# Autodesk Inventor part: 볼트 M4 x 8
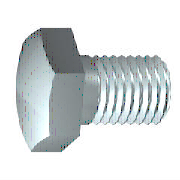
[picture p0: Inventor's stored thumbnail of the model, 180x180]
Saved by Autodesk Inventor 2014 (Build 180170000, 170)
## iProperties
Created: 2012-02
Part Number: 볼트 M4 x 8
Material: 스테인리스강
Description: 6각 머리 나사
Document SubType Name: Modeling
Standard: ISO 4017
Designer: mduedu
Standard Revision: Third edition 1999-08-15
Standards Organization: ISO
Language: ko-KR
Size Designation: M4 x 10
Categories: <MemberInstance><Categories><Category DisplayName="조임쇠" InternalName="e4da775c-781d-43d5-af7c-5136215cf5a6" Mnemonic="FSTN"><Category DisplayName="볼트" InternalN
Density: 8.08 g/cm^3
Appearance: 반광택
IsCustomPart: 0
Author: mduedu
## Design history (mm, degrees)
sketch "스케치1"
  geometry: L1 (0, 3.015)-(0, 2); L2 (1.75, 2)-(8, 2); L3 (8, 2)-(8, 0); L4 (8, 0)-(-0.4, 0); L5 (-2.08, 0)-(9.68, 0) reference; L6 (-0.4, 0)-(-0.4, 3.015); L7 (-0.4, 3.015)-(0, 3.015); L8 (1.75, 2)-(1.32, 2); L9 (1.32, 2)-(0, 2); L10 (0, -0.603)-(0, 3.618) reference
  constraints: 16 end point, 2 collinear, 2 perpendicular, 1 parallel
  dimensions: "d0" = 8 distance between parallel lines of L3 L1 (= NLG); "d1" = 6.25 distance from line of L2.start L3 (= GEL); "d2" = 4 diameter of L2 L4 (= GD); "d9" = 0.4001 distance between parallel lines of L6 L1 (computed from SD); "d10" = 6.03 diameter of L7 L4 (= SD2); "d13" = 0.42952 distance of L2.start L8.end (computed from GAL); "d14" = 4 diameter of L9 L4 (= BDM)
revolve "본체" sketch "스케치1" stored, may be unused: angle "d12" = 90 deg
sketch "스케치2"
  geometry: L1 (0, 4.041)-(3.5, 2.021); L2 (3.5, 2.021)-(3.5, -2.021); L3 (3.5, -2.021)-(0, -4.041); L4 (0, -4.041)-(-3.5, -2.021); L5 (-3.5, -2.021)-(-3.5, 2.021); L6 (-3.5, 2.021)-(0, 4.041); 2 further points
  constraints: 12 end point, 1 coincident, 1 vertical, 11 other
  dimensions: "d11" = 7 distance between parallel lines of L5 L2 (= SW)
extrude "머리" join sketch "스케치2" distance "d3" = 2.4 (= KOH - SD); taper "d4" = 0 deg
sketch "스케치4"
  geometry: L1 (-2.8, 3.5)-(-2.8, 4.041); L2 (-2.8, 4.041)-(-2.487, 4.041); L3 (-2.487, 4.041)-(-2.8, 3.5); L4 (-3.28, 0)-(0.08, 0) reference; L5 (-0.4, 4.041)-(-2.8, 4.041) reference; L6 (-2.8, 2.021)-(-2.8, 4.041) reference
  constraints: 6 end point, 2 collinear, 1 perpendicular, 1 vertical
  dimensions: "d5" = 30 deg angle of L3 L1 (= ANG1); "d19" = 7 diameter of L1.start L4 (= SW0)
revolve "모따기1" sketch "스케치4" stored, may be unused: angle "d21" = 90 deg
workplane "Work Plane1"
body "Solid1"
feature "스레드" dims "d15" = 6.25 (= GEL), "d16" = 0
chamfer "모따기2" distance "d6" = 0.42941 (= -0.5 x SPD + 0.5 x GD); stored, may be unused: second distance "d7" = 0.42952 (computed from GUL), angle "d55" = 45 deg
other parameters: "NLG" = 8 [user parameter; used in 1 equation term], "GD" = 4 (= NND) [user parameter; used in 2 equation terms], "BDM" = 4 (= NND) [user parameter; used in 1 equation term], "KOH" = 2.8 [user parameter; used in 1 equation term], "GEL" = 6.25 [user parameter; used in 2 equation terms], "SW" = 7 [user parameter; used in 2 equation terms], "SW0" = 7 (= SW) [user parameter; used in 1 equation term], "SPD" = 3.14117 (= NND - 1.2269 x PTC) [user parameter; used in 1 equation term], "SD2" = 6.03 [user parameter; used in 2 equation terms], "SD" = 0.4 [user parameter; used in 2 equation terms], "ANG1" = 30 deg [user parameter; used in 1 equation term], "GAL" = 0.42941 (= 0.61345 x PTC) [user parameter; used in 1 equation term], "GUL" = 0.42941 (= 0.61345 x PTC) [user parameter; used in 1 equation term], "d8" = 0, "RR" = 0.2 [user parameter], "d57" = 0, "d58" = 0, "TPU" = 14.28571 (computed from PTC) [user parameter], "GD1" = 3.14117 (= THREADDIA - 1.2269 x PTC) [user parameter], "THREADDIA" = 4 [user parameter; used in 1 equation term], "SDH" = 6.03 (= SD2) [user parameter], "SDHG" = 2.1 [user parameter], "TOA" = 30 deg [user parameter], "PTC" = 0.7 [user parameter; used in 5 equation terms], "NND" = 4 [user parameter; used in 3 equation terms], "E0" = 8.085 [user parameter]
